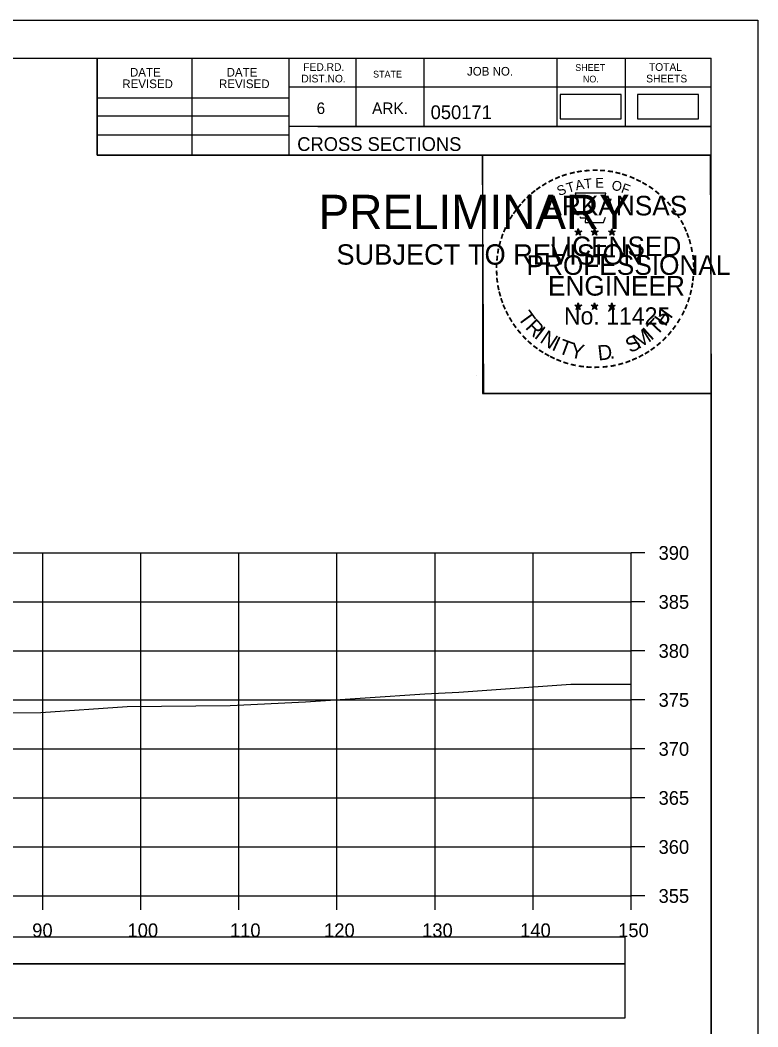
# Model space of a CAD drawing. Extents: x -37291014 to -37290680, y -936053 to -933067.
# Drawn here: x -37290755.4 to -37290680.2, y -935302.7 to -935200 of the extents above; entities that cross this region are included whole.
import ezdxf

# ---------------------------------------------------------------- set-up
doc = ezdxf.new("R2010")
doc.units = 0
for name, color, linetype in [('Default', 7, 'Continuous'), ('R_Axis', 7, 'Continuous'), ('R_Axis Annot', 7, 'Continuous'), ('R_Border', 7, 'Continuous'), ('R_Border PE', 7, 'Continuous'), ('R_Border Prem', 7, 'Continuous'), ('R_Exist Surface', 7, 'Continuous'), ('R_Grid', 7, 'Continuous'), ('R_No Plot', 7, 'Continuous')]:
    doc.layers.add(name, color=color, linetype=linetype)

msp = doc.modelspace()

# ---------------------------------------------------------------- linework, layer by layer
at = {"layer": 'Default'}
for points in [[(-37290700.35, -935210.02), (-37290694.1, -935210.02), (-37290694.1, -935207.54), (-37290700.35, -935207.54)], [(-37290692.46, -935210.03), (-37290686.21, -935210.03), (-37290686.21, -935207.55), (-37290692.46, -935207.55)], [(-37290992.48, -935296.22), (-37290693.72, -935296.22), (-37290693.72, -935293.51), (-37290992.48, -935293.51)], [(-37290992.48, -935301.74), (-37290693.72, -935301.74), (-37290693.72, -935296.22), (-37290992.48, -935296.22)]]:
    msp.add_lwpolyline(points, close=True, dxfattribs=at)
at = {"layer": 'R_Axis'}
for p, q in [((-37290693.1, -935289.31), (-37290693.1, -935254.31)), ((-37290691.7, -935254.31), (-37290693.1, -935254.31)), ((-37290691.7, -935259.31), (-37290693.1, -935259.31)), ((-37290691.7, -935264.31), (-37290693.1, -935264.31)), ((-37290691.7, -935269.31), (-37290693.1, -935269.31)), ((-37290691.7, -935274.31), (-37290693.1, -935274.31)), ((-37290691.7, -935279.31), (-37290693.1, -935279.31)), ((-37290691.7, -935284.31), (-37290693.1, -935284.31)), ((-37290993.1, -935289.31), (-37290693.1, -935289.31)), ((-37290753.1, -935290.71), (-37290753.1, -935289.31)), ((-37290743.1, -935290.71), (-37290743.1, -935289.31)), ((-37290733.1, -935290.71), (-37290733.1, -935289.31)), ((-37290723.1, -935290.71), (-37290723.1, -935289.31)), ((-37290713.1, -935290.71), (-37290713.1, -935289.31)), ((-37290703.1, -935290.71), (-37290703.1, -935289.31)), ((-37290693.1, -935290.71), (-37290693.1, -935289.31)), ((-37290691.7, -935289.31), (-37290693.1, -935289.31))]:
    msp.add_line(p, q, dxfattribs=at)
at = {"layer": 'R_Border'}
for p, q in [((-37291001.1, -935203.85), (-37290684.92, -935203.85)), ((-37290747.56, -935213.73), (-37290747.56, -935203.85)), ((-37290737.88, -935213.73), (-37290737.88, -935203.85)), ((-37290728.02, -935203.85), (-37290728.02, -935213.73)), ((-37290721.18, -935203.85), (-37290721.18, -935210.79)), ((-37290714.24, -935203.85), (-37290714.24, -935210.79)), ((-37290700.66, -935203.85), (-37290700.66, -935210.79)), ((-37290693.72, -935203.85), (-37290693.72, -935210.79)), ((-37290684.92, -935409.31), (-37290684.92, -935203.85)), ((-37290684.92, -935206.79), (-37290728.02, -935206.79)), ((-37290684.92, -935206.77), (-37290684.92, -935206.77)), ((-37290747.56, -935207.87), (-37290728.02, -935207.87)), ((-37290747.56, -935209.73), (-37290728.02, -935209.73)), ((-37290747.56, -935211.67), (-37290728.02, -935211.67)), ((-37290684.92, -935210.79), (-37290728.02, -935210.79)), ((-37290725.06, -935210.79), (-37290684.92, -935210.79)), ((-37290684.92, -935213.73), (-37290747.56, -935213.73))]:
    msp.add_line(p, q, dxfattribs=at)
at = {"layer": 'R_Border PE'}
for p, q in [((-37290698.84, -935221.47), (-37290698.49, -935221.59)), ((-37290698.84, -935221.47), (-37290698.58, -935221.52)), ((-37290698.84, -935221.47), (-37290698.6, -935221.6)), ((-37290698.7, -935221.88), (-37290698.49, -935221.59)), ((-37290698.7, -935221.88), (-37290698.58, -935221.64)), ((-37290698.7, -935221.88), (-37290698.49, -935221.67)), ((-37290698.49, -935221.22), (-37290698.53, -935221.47)), ((-37290698.49, -935221.59), (-37290698.49, -935221.22)), ((-37290698.49, -935221.22), (-37290698.44, -935221.47)), ((-37290698.14, -935221.47), (-37290698.49, -935221.59)), ((-37290698.27, -935221.88), (-37290698.49, -935221.59)), ((-37290698.27, -935221.88), (-37290698.49, -935221.67)), ((-37290698.14, -935221.47), (-37290698.43, -935221.52)), ((-37290698.27, -935221.88), (-37290698.41, -935221.59)), ((-37290698.14, -935221.47), (-37290698.34, -935221.58)), ((-37290697.17, -935221.47), (-37290696.82, -935221.59)), ((-37290697.17, -935221.47), (-37290696.91, -935221.52)), ((-37290697.17, -935221.47), (-37290696.93, -935221.6)), ((-37290697.03, -935221.88), (-37290696.82, -935221.59)), ((-37290697.03, -935221.88), (-37290696.91, -935221.64)), ((-37290697.03, -935221.88), (-37290696.82, -935221.67)), ((-37290696.82, -935221.22), (-37290696.86, -935221.47)), ((-37290696.82, -935221.59), (-37290696.82, -935221.22)), ((-37290696.82, -935221.22), (-37290696.77, -935221.47)), ((-37290696.47, -935221.47), (-37290696.82, -935221.59)), ((-37290696.6, -935221.88), (-37290696.82, -935221.59)), ((-37290696.6, -935221.88), (-37290696.82, -935221.67)), ((-37290696.47, -935221.47), (-37290696.76, -935221.52)), ((-37290696.6, -935221.88), (-37290696.74, -935221.59)), ((-37290696.47, -935221.47), (-37290696.67, -935221.58)), ((-37290695.4, -935221.49), (-37290695.05, -935221.6)), ((-37290695.4, -935221.49), (-37290695.15, -935221.53)), ((-37290695.4, -935221.49), (-37290695.17, -935221.61)), ((-37290695.27, -935221.89), (-37290695.05, -935221.6)), ((-37290695.27, -935221.89), (-37290695.14, -935221.65)), ((-37290695.27, -935221.89), (-37290695.06, -935221.68)), ((-37290695.05, -935221.23), (-37290695.09, -935221.48)), ((-37290694.84, -935221.89), (-37290695.06, -935221.68)), ((-37290695.05, -935221.6), (-37290695.05, -935221.23)), ((-37290695.05, -935221.23), (-37290695, -935221.48)), ((-37290694.71, -935221.49), (-37290695.05, -935221.6)), ((-37290694.84, -935221.89), (-37290695.05, -935221.6)), ((-37290694.71, -935221.49), (-37290694.99, -935221.54)), ((-37290694.84, -935221.89), (-37290694.98, -935221.6)), ((-37290694.71, -935221.49), (-37290694.91, -935221.59)), ((-37290698.84, -935229.05), (-37290698.49, -935229.16)), ((-37290698.84, -935229.05), (-37290698.59, -935229.09)), ((-37290698.84, -935229.05), (-37290698.6, -935229.17)), ((-37290698.71, -935229.46), (-37290698.49, -935229.16)), ((-37290698.49, -935228.79), (-37290698.53, -935229.05)), ((-37290698.49, -935229.16), (-37290698.49, -935228.79)), ((-37290698.49, -935228.79), (-37290698.44, -935229.04)), ((-37290698.14, -935229.05), (-37290698.49, -935229.16)), ((-37290698.28, -935229.46), (-37290698.49, -935229.16)), ((-37290698.14, -935229.05), (-37290698.43, -935229.1)), ((-37290698.28, -935229.46), (-37290698.42, -935229.16)), ((-37290698.14, -935229.05), (-37290698.35, -935229.15)), ((-37290697.17, -935229.05), (-37290696.82, -935229.16)), ((-37290697.17, -935229.05), (-37290696.92, -935229.09)), ((-37290697.17, -935229.05), (-37290696.93, -935229.17)), ((-37290697.04, -935229.46), (-37290696.82, -935229.16)), ((-37290696.82, -935228.79), (-37290696.86, -935229.05)), ((-37290696.82, -935229.16), (-37290696.82, -935228.79)), ((-37290696.82, -935228.79), (-37290696.77, -935229.04)), ((-37290696.48, -935229.05), (-37290696.82, -935229.16)), ((-37290696.61, -935229.46), (-37290696.82, -935229.16)), ((-37290696.48, -935229.05), (-37290696.76, -935229.1)), ((-37290696.61, -935229.46), (-37290696.75, -935229.16)), ((-37290696.48, -935229.05), (-37290696.68, -935229.15)), ((-37290695.4, -935229.06), (-37290695.06, -935229.17)), ((-37290695.4, -935229.06), (-37290695.15, -935229.1)), ((-37290695.4, -935229.06), (-37290695.17, -935229.18)), ((-37290695.27, -935229.47), (-37290695.06, -935229.17)), ((-37290695.06, -935228.8), (-37290695.1, -935229.06)), ((-37290695.06, -935229.17), (-37290695.06, -935228.8)), ((-37290695.06, -935228.8), (-37290695.01, -935229.05)), ((-37290694.71, -935229.06), (-37290695.06, -935229.17)), ((-37290694.84, -935229.47), (-37290695.06, -935229.17)), ((-37290694.71, -935229.06), (-37290694.99, -935229.11)), ((-37290694.84, -935229.47), (-37290694.98, -935229.17)), ((-37290694.71, -935229.06), (-37290694.91, -935229.16)), ((-37290698.71, -935229.46), (-37290698.58, -935229.21)), ((-37290698.71, -935229.46), (-37290698.49, -935229.24)), ((-37290698.28, -935229.46), (-37290698.49, -935229.24)), ((-37290697.04, -935229.46), (-37290696.91, -935229.21)), ((-37290697.04, -935229.46), (-37290696.82, -935229.24)), ((-37290696.61, -935229.46), (-37290696.82, -935229.24)), ((-37290695.27, -935229.47), (-37290695.15, -935229.22)), ((-37290695.27, -935229.47), (-37290695.06, -935229.25)), ((-37290694.84, -935229.47), (-37290695.06, -935229.25))]:
    msp.add_line(p, q, dxfattribs=at)
for points in [[(-37290698.8, -935217.6), (-37290698.53, -935218.42)], [(-37290695.28, -935218.52), (-37290695.14, -935218.23), (-37290695.83, -935218.26), (-37290695.68, -935217.6), (-37290698.8, -935217.6)], [(-37290698.3, -935220.02), (-37290698.3, -935220.11), (-37290697.74, -935220.13), (-37290697.79, -935220.6), (-37290695.92, -935220.6), (-37290695.72, -935220.06)], [(-37290698.49, -935221.22), (-37290698.27, -935221.88), (-37290698.84, -935221.47), (-37290698.14, -935221.47), (-37290698.7, -935221.88), (-37290698.49, -935221.22)], [(-37290696.82, -935221.22), (-37290696.6, -935221.88), (-37290697.17, -935221.47), (-37290696.47, -935221.47), (-37290697.03, -935221.88), (-37290696.82, -935221.22)], [(-37290695.05, -935221.23), (-37290694.84, -935221.89), (-37290695.4, -935221.49), (-37290694.71, -935221.49), (-37290695.27, -935221.89), (-37290695.05, -935221.23)], [(-37290698.49, -935228.79), (-37290698.28, -935229.46), (-37290698.84, -935229.05), (-37290698.14, -935229.05), (-37290698.71, -935229.46), (-37290698.49, -935228.79)], [(-37290696.82, -935228.79), (-37290696.61, -935229.46), (-37290697.17, -935229.05), (-37290696.48, -935229.05), (-37290697.04, -935229.46), (-37290696.82, -935228.79)], [(-37290695.06, -935228.8), (-37290694.84, -935229.47), (-37290695.4, -935229.06), (-37290694.71, -935229.06), (-37290695.27, -935229.47), (-37290695.06, -935228.8)]]:
    msp.add_lwpolyline(points, dxfattribs=at)
for centre, radius in [((-37290698.49, -935221.59), 0.172), ((-37290698.49, -935221.59), 0.145), ((-37290698.49, -935221.59), 0.116), ((-37290698.49, -935221.59), 0.0991), ((-37290698.49, -935221.59), 0.0747), ((-37290698.49, -935221.59), 0.0495), ((-37290698.49, -935221.59), 0.0296), ((-37290696.82, -935221.59), 0.172), ((-37290696.82, -935221.59), 0.145), ((-37290696.82, -935221.59), 0.116), ((-37290696.82, -935221.59), 0.0991), ((-37290696.82, -935221.59), 0.0747), ((-37290696.82, -935221.59), 0.0495), ((-37290696.82, -935221.59), 0.0296), ((-37290695.05, -935221.6), 0.172), ((-37290695.05, -935221.6), 0.145), ((-37290695.05, -935221.6), 0.116), ((-37290695.05, -935221.6), 0.0991), ((-37290695.05, -935221.6), 0.0747), ((-37290695.05, -935221.6), 0.0495), ((-37290695.05, -935221.6), 0.0296), ((-37290698.49, -935229.16), 0.172), ((-37290698.49, -935229.16), 0.145), ((-37290698.49, -935229.16), 0.116), ((-37290698.49, -935229.16), 0.0991), ((-37290698.49, -935229.16), 0.0747), ((-37290698.49, -935229.16), 0.0495), ((-37290698.49, -935229.16), 0.0296), ((-37290696.82, -935229.16), 0.172), ((-37290696.82, -935229.16), 0.145), ((-37290696.82, -935229.16), 0.116), ((-37290696.82, -935229.16), 0.0991), ((-37290696.82, -935229.16), 0.0747), ((-37290696.82, -935229.16), 0.0495), ((-37290696.82, -935229.16), 0.0296), ((-37290695.06, -935229.17), 0.172), ((-37290695.06, -935229.17), 0.145), ((-37290695.06, -935229.17), 0.116), ((-37290695.06, -935229.17), 0.0991), ((-37290695.06, -935229.17), 0.0747), ((-37290695.06, -935229.17), 0.0495), ((-37290695.06, -935229.17), 0.0296)]:
    msp.add_circle(centre, radius, dxfattribs=at)
at = {"layer": 'R_Exist Surface'}
msp.add_lwpolyline([(-37290759.24, -935270.65), (-37290753.3, -935270.58), (-37290744.52, -935269.98), (-37290733.99, -935269.87), (-37290726.33, -935269.5), (-37290714.15, -935268.69), (-37290710.66, -935268.51), (-37290699.24, -935267.71), (-37290693.1, -935267.69)], dxfattribs=at)
at = {"layer": 'R_Grid'}
for p, q in [((-37290993.1, -935254.31), (-37290693.1, -935254.31)), ((-37290753.1, -935289.31), (-37290753.1, -935254.31)), ((-37290743.1, -935289.31), (-37290743.1, -935254.31)), ((-37290733.1, -935289.31), (-37290733.1, -935254.31)), ((-37290723.1, -935289.31), (-37290723.1, -935254.31)), ((-37290713.1, -935289.31), (-37290713.1, -935254.31)), ((-37290703.1, -935289.31), (-37290703.1, -935254.31)), ((-37290693.1, -935289.31), (-37290693.1, -935254.31)), ((-37290993.1, -935259.31), (-37290693.1, -935259.31)), ((-37290993.1, -935264.31), (-37290693.1, -935264.31)), ((-37290993.1, -935269.31), (-37290693.1, -935269.31)), ((-37290993.1, -935274.31), (-37290693.1, -935274.31)), ((-37290993.1, -935279.31), (-37290693.1, -935279.31)), ((-37290993.1, -935284.31), (-37290693.1, -935284.31)), ((-37290993.1, -935289.31), (-37290693.1, -935289.31))]:
    msp.add_line(p, q, dxfattribs=at)
at = {"layer": 'R_No Plot'}
for p, q in [((-37291013.5, -935199.96), (-37290680.17, -935199.96)), ((-37290708.89, -935236.19), (-37290708.89, -935236.19))]:
    msp.add_line(p, q, dxfattribs=at)
for points in [[(-37291013.51, -935199.96), (-37290680.17, -935199.96), (-37290680.17, -935413.29), (-37291013.51, -935413.29)], [(-37290767.18, -935203.85), (-37290747.56, -935203.85), (-37290747.56, -935213.73), (-37290731.45, -935213.73), (-37290708.25, -935213.73), (-37290708.25, -935238.06), (-37290684.92, -935238.06), (-37290684.92, -935409.31), (-37291001.1, -935409.31), (-37291001.1, -935203.85)], [(-37290708.25, -935213.73), (-37290685.04, -935213.73), (-37290684.92, -935238.06), (-37290708.13, -935238.06)]]:
    msp.add_lwpolyline(points, close=True, dxfattribs=at)

# ---------------------------------------------------------------- texts
at = {"layer": 'R_Axis Annot'}
for s, p in [('390', (-37290690.3, -935255.01)), ('385', (-37290690.3, -935260.01)), ('380', (-37290690.3, -935265.01)), ('375', (-37290690.3, -935270.01)), ('370', (-37290690.3, -935275.01)), ('365', (-37290690.3, -935280.01)), ('360', (-37290690.3, -935285.01)), ('355', (-37290690.3, -935290.01)), ('90', (-37290754.19, -935293.51)), ('100', (-37290744.47, -935293.51)), ('110', (-37290734.02, -935293.51)), ('120', (-37290724.42, -935293.51)), ('130', (-37290714.42, -935293.51)), ('140', (-37290704.42, -935293.51)), ('150', (-37290694.42, -935293.51))]:
    msp.add_text(s, height=1.4, dxfattribs=at).set_placement(p)
at = {"layer": 'R_Border'}
for s, height, p in [('FED.RD.', 0.782, (-37290726.54, -935205.13)), ('SHEET', 0.684, (-37290698.8, -935205.13)), ('TOTAL', 0.782, (-37290691.28, -935205.13)), ('DATE', 0.879, (-37290744.22, -935205.71)), ('DATE', 0.879, (-37290734.36, -935205.71)), ('DIST.NO.', 0.782, (-37290726.74, -935206.31)), ('STATE', 0.684, (-37290719.42, -935205.81)), ('JOB NO.', 0.879, (-37290709.84, -935205.61)), ('SHEETS', 0.782, (-37290691.56, -935206.31)), ('REVISED', 0.879, (-37290745, -935206.89)), ('REVISED', 0.879, (-37290735.14, -935206.89)), ('NO.', 0.684, (-37290698.02, -935206.31)), ('6', 1.17, (-37290725.18, -935209.53)), ('ARK.', 1.172, (-37290719.52, -935209.53)), ('050171', 1.4, (-37290713.55, -935210.05)), ('CROSS SECTIONS', 1.4, (-37290727.16, -935213.3))]:
    msp.add_text(s, height=height, dxfattribs=at).set_placement(p)
at = {"layer": 'R_Border PE'}
for s, height, rotation, p in [('-', 1.6, 19.1761, (-37290700.05, -935216.47)), ('-', 1.6, 13.6302, (-37290699.3, -935216.23)), ('-', 1.6, 10.2193, (-37290698.62, -935216.07)), ('-', 1.6, 5.8968, (-37290697.89, -935215.96)), ('-', 1.6, 0.1862, (-37290697.12, -935215.88)), ('-', 1.6, 357.743, (-37290696.4, -935215.9)), ('-', 1.6, 352.1617, (-37290695.65, -935215.95)), ('-', 1.6, 347.2049, (-37290694.93, -935216.07)), ('-', 1.6, 342.3362, (-37290694.3, -935216.22)), ('-', 1.6, 337.8551, (-37290693.56, -935216.45)), ('-', 1.6, 34.0636, (-37290701.91, -935217.43)), ('-', 1.6, 28.7918, (-37290701.31, -935217.06)), ('-', 1.6, 24.3072, (-37290700.68, -935216.74)), ('S', 1, 21.594, (-37290700.44, -935217.92)), ('T', 1, 16.4036, (-37290699.53, -935217.59)), ('A', 1, 11.2132, (-37290698.7, -935217.34)), ('T', 1, 6.0228, (-37290697.85, -935217.17)), ('E', 1, 0.8323, (-37290696.75, -935217.06)), ('O', 1, 350.4515, (-37290695.14, -935217.27)), ('F', 1, 340.0707, (-37290694.19, -935217.5)), ('-', 1.6, 334.1211, (-37290692.93, -935216.72)), ('-', 1.6, 329.6409, (-37290692.35, -935217)), ('-', 1.6, 325.8627, (-37290691.71, -935217.36)), ('-', 1.6, 42.9622, (-37290703.4, -935218.62)), ('-', 1.6, 38.9507, (-37290702.97, -935218.2)), ('-', 1.6, 36.2317, (-37290702.49, -935217.82)), ('-', 1.6, 320.5297, (-37290691.1, -935217.79)), ('-', 1.6, 315.5786, (-37290690.5, -935218.27)), ('-', 1.6, 50.6142, (-37290704.25, -935219.58)), ('-', 1.6, 48.4231, (-37290703.85, -935219.09)), ('-', 1.6, 309.8797, (-37290689.93, -935218.82)), ('-', 1.6, 58.0706, (-37290704.99, -935220.67)), ('-', 1.6, 54.2325, (-37290704.66, -935220.15)), ('-', 1.6, 306.6522, (-37290689.41, -935219.43)), ('-', 1.4, 303.6753, (-37290688.92, -935219.99)), ('-', 1.6, 62.8713, (-37290705.3, -935221.29)), ('-', 1.6, 299.6684, (-37290688.6, -935220.6)), ('-', 1.6, 72.3945, (-37290705.78, -935222.53)), ('-', 1.6, 67.7743, (-37290705.56, -935221.9)), ('-', 1.6, 294.6628, (-37290688.28, -935221.21)), ('-', 1.6, 290.5728, (-37290688.02, -935221.79)), ('-', 1.6, 75.461, (-37290705.98, -935223.24)), ('-', 1.6, 285.1233, (-37290687.79, -935222.37)), ('-', 1.6, 85.1863, (-37290706.18, -935224.65)), ('-', 1.6, 81.2013, (-37290706.11, -935223.96)), ('-', 1.6, 280.5493, (-37290687.59, -935223.11)), ('-', 1.6, 276.5962, (-37290687.42, -935223.88)), ('-', 1.6, 89.0622, (-37290706.21, -935225.35)), ('-', 1.6, 274.3301, (-37290687.36, -935224.6)), ('-', 1.6, 94.1959, (-37290706.17, -935226.07)), ('-', 1.6, 263.5172, (-37290687.35, -935225.9)), ('-', 1.6, 269.9407, (-37290687.33, -935225.23)), ('-', 1.6, 98.9479, (-37290706.1, -935226.74)), ('-', 1.6, 101.7149, (-37290705.97, -935227.47)), ('-', 1.6, 260.9953, (-37290687.42, -935226.55)), ('-', 1.6, 105.4578, (-37290705.8, -935228.07)), ('-', 1.6, 255.7626, (-37290687.53, -935227.23)), ('-', 1.6, 109.0874, (-37290705.59, -935228.7)), ('-', 1.6, 114.0643, (-37290705.34, -935229.29)), ('-', 1.6, 247.8887, (-37290687.93, -935228.63)), ('-', 1.6, 252.8681, (-37290687.71, -935227.95)), ('-', 1.6, 115.7289, (-37290705.03, -935229.91)), ('T', 1.54, 306.0406, (-37290704.73, -935230.32)), ('H', 1.54, 54.6088, (-37290689.61, -935231.29)), ('-', 1.6, 244.6197, (-37290688.2, -935229.25)), ('-', 1.6, 120.4471, (-37290704.67, -935230.5)), ('-', 1.6, 125.8934, (-37290704.27, -935231.06)), ('R', 1.54, 314.005, (-37290703.97, -935231.37)), ('I', 1.54, 321.9694, (-37290703.07, -935232.3)), ('T', 1.54, 46.6444, (-37290690.5, -935232.23)), ('-', 1.6, 233.8452, (-37290688.99, -935230.66)), ('-', 1.6, 239.0712, (-37290688.59, -935230.01)), ('-', 1.6, 130.7181, (-37290703.81, -935231.61)), ('-', 1.6, 134.2238, (-37290703.29, -935232.16)), ('N', 1.54, 326.5002, (-37290702.5, -935232.77)), ('I', 1.54, 335.3603, (-37290701.29, -935233.56)), ('S', 1.54, 26.9312, (-37290693.19, -935233.96)), ('M', 1.54, 32.6563, (-37290692.35, -935233.55)), ('I', 1.54, 42.1136, (-37290691.06, -935232.71)), ('-', 1.6, 225.7653, (-37290689.9, -935231.79)), ('-', 1.6, 231.2538, (-37290689.42, -935231.23)), ('-', 1.6, 138.9338, (-37290702.77, -935232.62)), ('-', 1.6, 144.6463, (-37290702.21, -935233.03)), ('T', 1.54, 339.8912, (-37290700.63, -935233.89)), ('Y', 1.54, 347.8556, (-37290699.42, -935234.33)), ('D', 1.54, 6.3969, (-37290696.43, -935234.69)), ('-', 1.6, 215.7363, (-37290690.97, -935232.77)), ('-', 1.6, 221.0851, (-37290690.42, -935232.3)), ('-', 1.6, 148.0898, (-37290701.65, -935233.4)), ('-', 1.6, 151.5704, (-37290701.07, -935233.72)), ('-', 1.6, 154.6002, (-37290700.55, -935233.97)), ('.', 1.54, 13.7642, (-37290695.24, -935234.56)), ('-', 1.6, 207.3568, (-37290692.06, -935233.5)), ('-', 1.6, 212.2491, (-37290691.51, -935233.16)), ('-', 1.6, 158.5612, (-37290699.92, -935234.22)), ('-', 1.6, 162.7983, (-37290699.24, -935234.44)), ('-', 1.6, 167.5555, (-37290698.52, -935234.6)), ('-', 1.6, 173.1155, (-37290697.75, -935234.71)), ('-', 1.6, 176.5183, (-37290697, -935234.76)), ('-', 1.6, 181.5918, (-37290696.26, -935234.74)), ('-', 1.6, 185.8167, (-37290695.45, -935234.67)), ('-', 1.6, 191.2858, (-37290694.71, -935234.54)), ('-', 1.6, 195.4743, (-37290693.98, -935234.34)), ('-', 1.6, 200.7184, (-37290693.31, -935234.1)), ('-', 1.6, 204.2516, (-37290692.69, -935233.82))]:
    msp.add_text(s, height=height, rotation=rotation, dxfattribs=at).set_placement(p)
for s, height, p in [('ARKANSAS', 2, (-37290701.94, -935219.88)), ('DWB', 0.01, (-37290698.5, -935221.59)), ('DWB', 0.01, (-37290696.83, -935221.59)), ('DWB', 0.01, (-37290695.07, -935221.6)), ('LICENSED', 2, (-37290701.35, -935224.03)), ('PROFESSIONAL', 2, (-37290703.77, -935225.94)), ('ENGINEER', 2, (-37290701.58, -935228.06)), ('DWB', 0.01, (-37290698.5, -935229.16)), ('DWB', 0.01, (-37290696.84, -935229.16)), ('DWB', 0.01, (-37290695.07, -935229.17)), ('No. 11425', 1.757, (-37290699.95, -935231.01))]:
    msp.add_text(s, height=height, dxfattribs=at).set_placement(p)
at = {"layer": 'R_Border Prem'}
for s, height, p in [('PRELIMINARY', 3.5, (-37290724.97, -935221.27)), ('DWB', 0.01, (-37290724.22, -935219.42)), ('SUBJECT TO REVISION', 2.0751, (-37290723.16, -935224.9))]:
    msp.add_text(s, height=height, dxfattribs=at).set_placement(p)

doc.saveas('drawing.dxf')
